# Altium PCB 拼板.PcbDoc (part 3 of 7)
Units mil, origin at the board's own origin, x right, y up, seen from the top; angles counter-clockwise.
Board outline 3630.03 x 5330.03 mil, 2 copper layers (Top Layer, Bottom Layer); 416 components, 35 nets, 1936 pads, 800 vias.
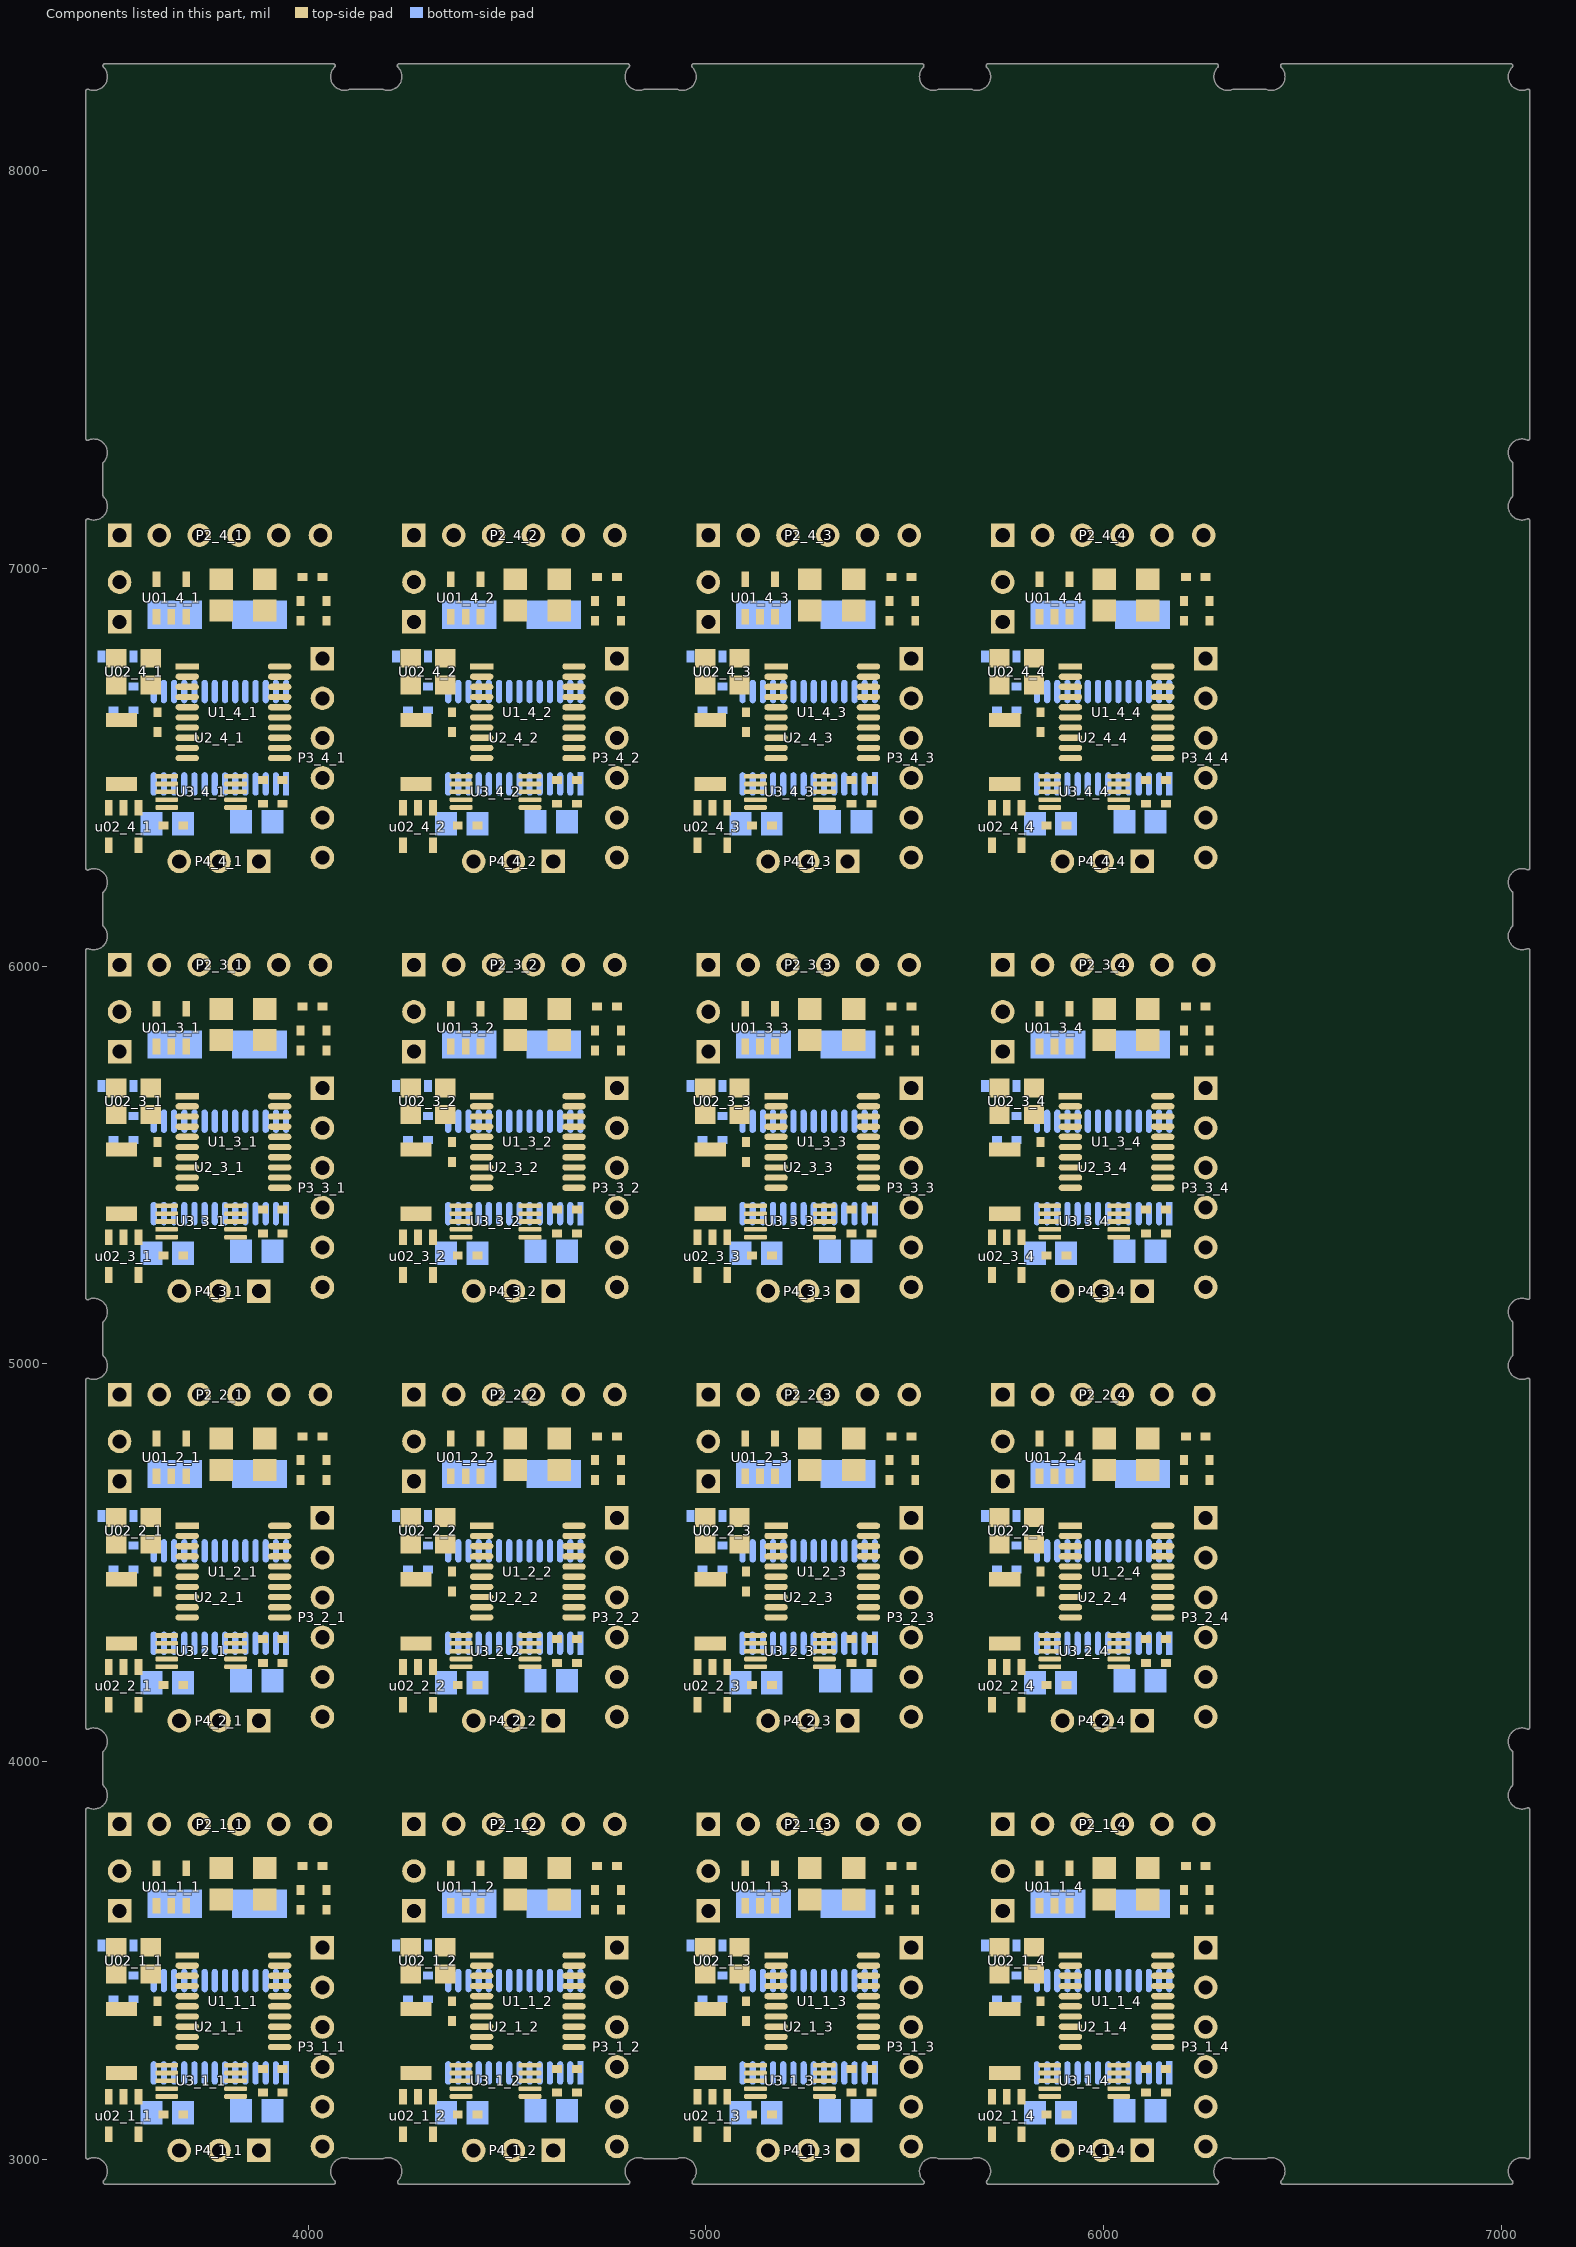
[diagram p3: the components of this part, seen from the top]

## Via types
v1: diameter 24, hole 24, Top Layer to Bottom Layer, 480 vias
v2: diameter 20, hole 10, Top Layer to Bottom Layer, 240 vias
v3: diameter 36, hole 20, Top Layer to Bottom Layer, 48 vias
v4: diameter 32, hole 16, Top Layer to Bottom Layer, 32 vias

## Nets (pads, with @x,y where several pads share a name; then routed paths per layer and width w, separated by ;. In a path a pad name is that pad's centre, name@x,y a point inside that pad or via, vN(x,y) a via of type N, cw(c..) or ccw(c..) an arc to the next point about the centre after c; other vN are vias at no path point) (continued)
copper on no net: | length 270841.8
  Top Layer w8: 3517.76,3466.64 3519.73,3466.64 3552.35,3499.26 3634.83,3499.26 3668.37,3465.71 3668.44,3465.71 3672.32,3461.84 3696.07,3461.84 ; 3517.76,4546.64 3519.73,4546.64 3552.35,4579.26 3634.83,4579.26 3668.37,4545.71 3668.44,4545.71 3672.32,4541.84 3696.07,4541.84 ; 3517.76,5626.64 3519.73,5626.64 3552.35,5659.26 3634.83,5659.26 3668.37,5625.71 3668.44,5625.71 3672.32,5621.84 3696.07,5621.84 ; 3517.76,6706.64 3519.73,6706.64 3552.35,6739.26 3634.83,6739.26 3668.37,6705.71 3668.44,6705.71 3672.32,6701.84 3696.07,6701.84 ; 3526.78,3378.02 3601.07,3378.02 3621.07,3398.02 3627.03,3392.06 3647.03,3392.06 3652.99,3386.1 3695.04,3386.1 3696.07,3385.07 ; 3526.78,4458.02 3601.07,4458.02 3621.07,4478.02 3627.03,4472.06 3647.03,4472.06 3652.99,4466.1 3695.04,4466.1 3696.07,4465.07 ; 3526.78,5538.02 3601.07,5538.02 3621.07,5558.02 3627.03,5552.06 3647.03,5552.06 3652.99,5546.1 3695.04,5546.1 3696.07,5545.07 ; 3526.78,6618.02 3601.07,6618.02 3621.07,6638.02 3627.03,6632.06 3647.03,6632.06 3652.99,6626.1 3695.04,6626.1 3696.07,6625.07 ; 3573.47,3083.53 3602.96,3113.02 3636.07,3113.02 ; 3573.47,4163.53 3602.96,4193.02 3636.07,4193.02 ; 3573.47,5243.53 3602.96,5273.02 3636.07,5273.02 ; 3573.47,6323.53 3602.96,6353.02 3636.07,6353.02 ; 3614.61,3523.34 3624,3513.95 3642.42,3513.95 3667.45,3488.91 3694.58,3488.91 3696.07,3487.43 ; 3614.61,4603.34 3624,4593.95 3642.42,4593.95 3667.45,4568.91 3694.58,4568.91 3696.07,4567.43 ; 3614.61,5683.34 3624,5673.95 3642.42,5673.95 3667.45,5648.91 3694.58,5648.91 3696.07,5647.43 ; 3614.61,6763.34 3624,6753.95 3642.42,6753.95 3667.45,6728.91 3694.58,6728.91 3696.07,6727.43 ; 3644.45,3158.65 3644.45,3119.02 3638.45,3113.02 3636.07,3113.02 ; 3644.45,3237.39 3749.65,3237.39 3820.56,3308.3 3928.35,3308.3 ; 3644.45,4238.65 3644.45,4199.02 3638.45,4193.02 3636.07,4193.02 ; 3644.45,4317.39 3749.65,4317.39 3820.56,4388.3 3928.35,4388.3 ; 3644.45,5318.65 3644.45,5279.02 3638.45,5273.02 3636.07,5273.02 ; 3644.45,5397.39 3749.65,5397.39 3820.56,5468.3 3928.35,5468.3 ; 3644.45,6398.65 3644.45,6359.02 3638.45,6353.02 3636.07,6353.02 ; 3644.45,6477.39 3749.65,6477.39 3820.56,6548.3 3928.35,6548.3 ; 3696.07,3282.71 3747.5,3282.71 3752.82,3288.02 v2(3756.07,3288.02) ; 3696.07,3308.3 3696.34,3308.02 v2(3736.07,3308.02) ; 3696.07,3333.89 3749.13,3333.89 3760.51,3322.51 v2(3796.07,3322.51) ; 3696.07,3359.48 3751.01,3359.48 3768.98,3341.51 v2(3771.48,3341.51) ; 3696.07,3513.02 3717.72,3513.02 v2(3752.72,3548.02) ; 3696.07,4362.71 3747.5,4362.71 3752.82,4368.02 v2(3756.07,4368.02) ; 3696.07,4388.3 3696.34,4388.02 v2(3736.07,4388.02) ; 3696.07,4413.89 3749.13,4413.89 3760.51,4402.51 v2(3796.07,4402.51) ; 3696.07,4439.48 3751.01,4439.48 3768.98,4421.51 v2(3771.48,4421.51) ; 3696.07,4593.02 3717.72,4593.02 v2(3752.72,4628.02) ; 3696.07,5442.71 3747.5,5442.71 3752.82,5448.02 v2(3756.07,5448.02) ; 3696.07,5468.3 3696.34,5468.02 v2(3736.07,5468.02) ; 3696.07,5493.89 3749.13,5493.89 3760.51,5482.51 v2(3796.07,5482.51) ; 3696.07,5519.48 3751.01,5519.48 3768.98,5501.51 v2(3771.48,5501.51) ; 3696.07,5673.02 3717.72,5673.02 v2(3752.72,5708.02) ; 3696.07,6522.71 3747.5,6522.71 3752.82,6528.02 v2(3756.07,6528.02) ; 3696.07,6548.3 3696.34,6548.02 v2(3736.07,6548.02) ; 3696.07,6573.89 3749.13,6573.89 3760.51,6562.51 v2(3796.07,6562.51) ; 3696.07,6599.48 3751.01,6599.48 3768.98,6581.51 v2(3771.48,6581.51) ; 3696.07,6753.02 3717.72,6753.02 v2(3752.72,6788.02) ; v2(3806.07,3548.02) 3892.25,3461.84 3928.35,3461.84 ; v2(3806.07,4628.02) 3892.25,4541.84 3928.35,4541.84 ; v2(3806.07,5708.02) 3892.25,5621.84 3928.35,5621.84 ; v2(3806.07,6788.02) 3892.25,6701.84 3928.35,6701.84 ; v2(3816.07,3413.02) 3878.74,3413.02 3906.7,3385.07 3928.35,3385.07 ; v2(3816.07,4493.02) 3878.74,4493.02 3906.7,4465.07 3928.35,4465.07 ; v2(3816.07,5573.02) 3878.74,5573.02 3906.7,5545.07 3928.35,5545.07 ; v2(3816.07,6653.02) 3878.74,6653.02 3906.7,6625.07 3928.35,6625.07 ; 3817.68,3158.65 3771.7,3158.65 3704,3090.96 3663.13,3090.96 3647.07,3107.02 3642.07,3107.02 3636.07,3113.02 ; 3817.68,3217.71 3816.85,3218.54 3784.82,3218.54 3780.14,3223.23 3780.14,3245.3 3830.14,3295.3 3868.19,3295.3 3880.78,3282.71 3928.35,3282.71 ; 3817.68,4238.65 3771.7,4238.65 3704,4170.96 3663.13,4170.96 3647.07,4187.02 3642.07,4187.02 3636.07,4193.02 ; 3817.68,4297.71 3816.85,4298.54 3784.82,4298.54 3780.14,4303.23 3780.14,4325.3 3830.14,4375.3 3868.19,4375.3 3880.78,4362.71 3928.35,4362.71 ; 3817.68,5318.65 3771.7,5318.65 3704,5250.96 3663.13,5250.96 3647.07,5267.02 3642.07,5267.02 3636.07,5273.02 ; 3817.68,5377.71 3816.85,5378.54 3784.82,5378.54 3780.14,5383.23 3780.14,5405.3 3830.14,5455.3 3868.19,5455.3 3880.78,5442.71 3928.35,5442.71 ; 3817.68,6398.65 3771.7,6398.65 3704,6330.96 3663.13,6330.96 3647.07,6347.02 3642.07,6347.02 3636.07,6353.02 ; 3817.68,6457.71 3816.85,6458.54 3784.82,6458.54 3780.14,6463.23 3780.14,6485.3 3830.14,6535.3 3868.19,6535.3 3880.78,6522.71 3928.35,6522.71 ; v2(3836.07,3373.02) 3846.07,3373.02 3883.72,3335.37 3926.87,3335.37 3928.35,3333.89 ; v2(3836.07,4453.02) 3846.07,4453.02 3883.72,4415.37 3926.87,4415.37 3928.35,4413.89 ; v2(3836.07,5533.02) 3846.07,5533.02 3883.72,5495.37 3926.87,5495.37 3928.35,5493.89 ; v2(3836.07,6613.02) 3846.07,6613.02 3883.72,6575.37 3926.87,6575.37 3928.35,6573.89 ; v2(3836.92,3548.02) 3836.92,3543.35 3892.84,3487.43 3928.35,3487.43 ; v2(3836.92,4628.02) 3836.92,4623.35 3892.84,4567.43 3928.35,4567.43 ; v2(3836.92,5708.02) 3836.92,5703.35 3892.84,5647.43 3928.35,5647.43 ; v2(3836.92,6788.02) 3836.92,6783.35 3892.84,6727.43 3928.35,6727.43 ; v2(3866.07,3390.52) 3866.07,3388.02 3893.13,3360.96 3926.87,3360.96 3928.35,3359.48 ; v2(3866.07,3548.02) 3866.07,3544.22 3895.92,3514.36 3927.02,3514.36 3928.35,3513.02 ; v2(3866.07,4470.52) 3866.07,4468.02 3893.13,4440.96 3926.87,4440.96 3928.35,4439.48 ; v2(3866.07,4628.02) 3866.07,4624.22 3895.92,4594.36 3927.02,4594.36 3928.35,4593.02 ; v2(3866.07,5550.52) 3866.07,5548.02 3893.13,5520.96 3926.87,5520.96 3928.35,5519.48 ; v2(3866.07,5708.02) 3866.07,5704.22 3895.92,5674.36 3927.02,5674.36 3928.35,5673.02 ; v2(3866.07,6630.52) 3866.07,6628.02 3893.13,6600.96 3926.87,6600.96 3928.35,6599.48 ; v2(3866.07,6788.02) 3866.07,6784.22 3895.92,6754.36 3927.02,6754.36 3928.35,6753.02 ; 3886.07,3168.02 3892.07,3174.02 3902.07,3174.02 v2(3921.07,3193.02) ; 3886.07,4248.02 3892.07,4254.02 3902.07,4254.02 v2(3921.07,4273.02) ; 3886.07,5328.02 3892.07,5334.02 3902.07,5334.02 v2(3921.07,5353.02) ; 3886.07,6408.02 3892.07,6414.02 3902.07,6414.02 v2(3921.07,6433.02) ; 3928.35,3410.66 3952.1,3410.66 4029.74,3333.02 4036.07,3333.02 ; 3928.35,3436.25 3929.83,3434.77 4034.32,3434.77 4036.07,3433.02 ; 3928.35,4490.66 3952.1,4490.66 4029.74,4413.02 4036.07,4413.02 ; 3928.35,4516.25 3929.83,4514.77 4034.32,4514.77 4036.07,4513.02 ; 3928.35,5570.66 3952.1,5570.66 4029.74,5493.02 4036.07,5493.02 ; 3928.35,5596.25 3929.83,5594.77 4034.32,5594.77 4036.07,5593.02 ; 3928.35,6650.66 3952.1,6650.66 4029.74,6573.02 4036.07,6573.02 ; 3928.35,6676.25 3929.83,6674.77 4034.32,6674.77 4036.07,6673.02 ; 3936.07,3168.02 3938.57,3168.02 3944.57,3174.02 3944.57,3183.27 3951.07,3189.77 v2(3951.07,3193.02) ; 3936.07,3228.02 3939.07,3225.02 3956.76,3225.02 3970.07,3211.72 3970.07,3144.02 v2(3976.07,3138.02) ; 3936.07,4248.02 3938.57,4248.02 3944.57,4254.02 3944.57,4263.27 3951.07,4269.77 v2(3951.07,4273.02) ; 3936.07,4308.02 3939.07,4305.02 3956.76,4305.02 3970.07,4291.72 3970.07,4224.02 v2(3976.07,4218.02) ; 3936.07,5328.02 3938.57,5328.02 3944.57,5334.02 3944.57,5343.27 3951.07,5349.77 v2(3951.07,5353.02) ; 3936.07,5388.02 3939.07,5385.02 3956.76,5385.02 3970.07,5371.72 3970.07,5304.02 v2(3976.07,5298.02) ; 3936.07,6408.02 3938.57,6408.02 3944.57,6414.02 3944.57,6423.27 3951.07,6429.77 v2(3951.07,6433.02) ; 3936.07,6468.02 3939.07,6465.02 3956.76,6465.02 3970.07,6451.72 3970.07,6384.02 v2(3976.07,6378.02) ; 4257.76,3466.64 4259.73,3466.64 4292.35,3499.26 4374.83,3499.26 4408.37,3465.71 4408.44,3465.71 4412.32,3461.84 4436.07,3461.84 ; 4257.76,4546.64 4259.73,4546.64 4292.35,4579.26 4374.83,4579.26 4408.37,4545.71 4408.44,4545.71 4412.32,4541.84 4436.07,4541.84 ; 4257.76,5626.64 4259.73,5626.64 4292.35,5659.26 4374.83,5659.26 4408.37,5625.71 4408.44,5625.71 4412.32,5621.84 4436.07,5621.84 ; 4257.76,6706.64 4259.73,6706.64 4292.35,6739.26 4374.83,6739.26 4408.37,6705.71 4408.44,6705.71 4412.32,6701.84 4436.07,6701.84 ; 4266.78,3378.02 4341.07,3378.02 4361.07,3398.02 4367.03,3392.06 4387.03,3392.06 4392.99,3386.1 4435.04,3386.1 4436.07,3385.07 ; 4266.78,4458.02 4341.07,4458.02 4361.07,4478.02 4367.03,4472.06 4387.03,4472.06 4392.99,4466.1 4435.04,4466.1 4436.07,4465.07 ; 4266.78,5538.02 4341.07,5538.02 4361.07,5558.02 4367.03,5552.06 4387.03,5552.06 4392.99,5546.1 4435.04,5546.1 4436.07,5545.07 ; 4266.78,6618.02 4341.07,6618.02 4361.07,6638.02 4367.03,6632.06 4387.03,6632.06 4392.99,6626.1 4435.04,6626.1 4436.07,6625.07 ; 4313.47,3083.53 4342.96,3113.02 4376.07,3113.02 ; 4313.47,4163.53 4342.96,4193.02 4376.07,4193.02 ; 4313.47,5243.53 4342.96,5273.02 4376.07,5273.02 ; 4313.47,6323.53 4342.96,6353.02 4376.07,6353.02 ; 4354.61,3523.34 4364,3513.95 4382.42,3513.95 4407.45,3488.91 4434.58,3488.91 4436.07,3487.43 ; 4354.61,4603.34 4364,4593.95 4382.42,4593.95 4407.45,4568.91 4434.58,4568.91 4436.07,4567.43 ; 4354.61,5683.34 4364,5673.95 4382.42,5673.95 4407.45,5648.91 4434.58,5648.91 4436.07,5647.43 ; 4354.61,6763.34 4364,6753.95 4382.42,6753.95 4407.45,6728.91 4434.58,6728.91 4436.07,6727.43 ; 4384.45,3158.65 4384.45,3119.02 4378.45,3113.02 4376.07,3113.02 ; 4384.45,3237.39 4489.65,3237.39 4560.56,3308.3 4668.35,3308.3 ; 4384.45,4238.65 4384.45,4199.02 4378.45,4193.02 4376.07,4193.02 ; 4384.45,4317.39 4489.65,4317.39 4560.56,4388.3 4668.35,4388.3 ; 4384.45,5318.65 4384.45,5279.02 4378.45,5273.02 4376.07,5273.02 ; 4384.45,5397.39 4489.65,5397.39 4560.56,5468.3 4668.35,5468.3 ; 4384.45,6398.65 4384.45,6359.02 4378.45,6353.02 4376.07,6353.02 ; 4384.45,6477.39 4489.65,6477.39 4560.56,6548.3 4668.35,6548.3 ; 4436.07,3282.71 4487.5,3282.71 4492.82,3288.02 v2(4496.07,3288.02) ; 4436.07,3308.3 4436.34,3308.02 v2(4476.07,3308.02) ; 4436.07,3333.89 4489.13,3333.89 4500.51,3322.51 v2(4536.07,3322.51) ; 4436.07,3359.48 4491.01,3359.48 4508.98,3341.51 v2(4511.48,3341.51) ; 4436.07,3513.02 4457.72,3513.02 v2(4492.72,3548.02) ; 4436.07,4362.71 4487.5,4362.71 4492.82,4368.02 v2(4496.07,4368.02) ; 4436.07,4388.3 4436.34,4388.02 v2(4476.07,4388.02) ; 4436.07,4413.89 4489.13,4413.89 4500.51,4402.51 v2(4536.07,4402.51) ; 4436.07,4439.48 4491.01,4439.48 4508.98,4421.51 v2(4511.48,4421.51) ; 4436.07,4593.02 4457.72,4593.02 v2(4492.72,4628.02) ; 4436.07,5442.71 4487.5,5442.71 4492.82,5448.02 v2(4496.07,5448.02) ; 4436.07,5468.3 4436.34,5468.02 v2(4476.07,5468.02) ; 4436.07,5493.89 4489.13,5493.89 4500.51,5482.51 v2(4536.07,5482.51) ; 4436.07,5519.48 4491.01,5519.48 4508.98,5501.51 v2(4511.48,5501.51) ; 4436.07,5673.02 4457.72,5673.02 v2(4492.72,5708.02) ; 4436.07,6522.71 4487.5,6522.71 4492.82,6528.02 v2(4496.07,6528.02) ; 4436.07,6548.3 4436.34,6548.02 v2(4476.07,6548.02) ; 4436.07,6573.89 4489.13,6573.89 4500.51,6562.51 v2(4536.07,6562.51) ; 4436.07,6599.48 4491.01,6599.48 4508.98,6581.51 v2(4511.48,6581.51) ; 4436.07,6753.02 4457.72,6753.02 v2(4492.72,6788.02) ; v2(4546.07,3548.02) 4632.25,3461.84 4668.35,3461.84 ; v2(4546.07,4628.02) 4632.25,4541.84 4668.35,4541.84 ; v2(4546.07,5708.02) 4632.25,5621.84 4668.35,5621.84 ; v2(4546.07,6788.02) 4632.25,6701.84 4668.35,6701.84 ; v2(4556.07,3413.02) 4618.74,3413.02 4646.7,3385.07 4668.35,3385.07 ; v2(4556.07,4493.02) 4618.74,4493.02 4646.7,4465.07 4668.35,4465.07 ; v2(4556.07,5573.02) 4618.74,5573.02 4646.7,5545.07 4668.35,5545.07 ; v2(4556.07,6653.02) 4618.74,6653.02 4646.7,6625.07 4668.35,6625.07 ; 4557.68,3158.65 4511.7,3158.65 4444,3090.96 4403.13,3090.96 4387.07,3107.02 4382.07,3107.02 4376.07,3113.02 ; 4557.68,3217.71 4556.85,3218.54 4524.82,3218.54 4520.14,3223.23 4520.14,3245.3 4570.14,3295.3 4608.19,3295.3 4620.78,3282.71 4668.35,3282.71 ; 4557.68,4238.65 4511.7,4238.65 4444,4170.96 4403.13,4170.96 4387.07,4187.02 4382.07,4187.02 4376.07,4193.02 ; 4557.68,4297.71 4556.85,4298.54 4524.82,4298.54 4520.14,4303.23 4520.14,4325.3 4570.14,4375.3 4608.19,4375.3 4620.78,4362.71 4668.35,4362.71 ; 4557.68,5318.65 4511.7,5318.65 4444,5250.96 4403.13,5250.96 4387.07,5267.02 4382.07,5267.02 4376.07,5273.02 ; 4557.68,5377.71 4556.85,5378.54 4524.82,5378.54 4520.14,5383.23 4520.14,5405.3 4570.14,5455.3 4608.19,5455.3 4620.78,5442.71 4668.35,5442.71 ; 4557.68,6398.65 4511.7,6398.65 4444,6330.96 4403.13,6330.96 4387.07,6347.02 4382.07,6347.02 4376.07,6353.02 ; 4557.68,6457.71 4556.85,6458.54 4524.82,6458.54 4520.14,6463.23 4520.14,6485.3 4570.14,6535.3 4608.19,6535.3 4620.78,6522.71 4668.35,6522.71 ; v2(4576.07,3373.02) 4586.07,3373.02 4623.72,3335.37 4666.87,3335.37 4668.35,3333.89 ; v2(4576.07,4453.02) 4586.07,4453.02 4623.72,4415.37 4666.87,4415.37 4668.35,4413.89 ; v2(4576.07,5533.02) 4586.07,5533.02 4623.72,5495.37 4666.87,5495.37 4668.35,5493.89 ; v2(4576.07,6613.02) 4586.07,6613.02 4623.72,6575.37 4666.87,6575.37 4668.35,6573.89 ; v2(4576.92,3548.02) 4576.92,3543.35 4632.84,3487.43 4668.35,3487.43 ; v2(4576.92,4628.02) 4576.92,4623.35 4632.84,4567.43 4668.35,4567.43 ; v2(4576.92,5708.02) 4576.92,5703.35 4632.84,5647.43 4668.35,5647.43 ; v2(4576.92,6788.02) 4576.92,6783.35 4632.84,6727.43 4668.35,6727.43 ; v2(4606.07,3390.52) 4606.07,3388.02 4633.13,3360.96 4666.87,3360.96 4668.35,3359.48 ; v2(4606.07,3548.02) 4606.07,3544.22 4635.92,3514.36 4667.02,3514.36 4668.35,3513.02 ; v2(4606.07,4470.52) 4606.07,4468.02 4633.13,4440.96 4666.87,4440.96 4668.35,4439.48 ; v2(4606.07,4628.02) 4606.07,4624.22 4635.92,4594.36 4667.02,4594.36 4668.35,4593.02 ; v2(4606.07,5550.52) 4606.07,5548.02 4633.13,5520.96 4666.87,5520.96 4668.35,5519.48 ; v2(4606.07,5708.02) 4606.07,5704.22 4635.92,5674.36 4667.02,5674.36 4668.35,5673.02 ; v2(4606.07,6630.52) 4606.07,6628.02 4633.13,6600.96 4666.87,6600.96 4668.35,6599.48 ; v2(4606.07,6788.02) 4606.07,6784.22 4635.92,6754.36 4667.02,6754.36 4668.35,6753.02 ; 4626.07,3168.02 4632.07,3174.02 4642.07,3174.02 v2(4661.07,3193.02) ; 4626.07,4248.02 4632.07,4254.02 4642.07,4254.02 v2(4661.07,4273.02) ; 4626.07,5328.02 4632.07,5334.02 4642.07,5334.02 v2(4661.07,5353.02) ; 4626.07,6408.02 4632.07,6414.02 4642.07,6414.02 v2(4661.07,6433.02) ; 4668.35,3410.66 4692.1,3410.66 4769.74,3333.02 4776.07,3333.02 ; 4668.35,3436.25 4669.83,3434.77 4774.32,3434.77 4776.07,3433.02 ; 4668.35,4490.66 4692.1,4490.66 4769.74,4413.02 4776.07,4413.02 ; 4668.35,4516.25 4669.83,4514.77 4774.32,4514.77 4776.07,4513.02 ; 4668.35,5570.66 4692.1,5570.66 4769.74,5493.02 4776.07,5493.02 ; 4668.35,5596.25 4669.83,5594.77 4774.32,5594.77 4776.07,5593.02 ; 4668.35,6650.66 4692.1,6650.66 4769.74,6573.02 4776.07,6573.02 ; 4668.35,6676.25 4669.83,6674.77 4774.32,6674.77 4776.07,6673.02 ; 4676.07,3168.02 4678.57,3168.02 4684.57,3174.02 4684.57,3183.27 4691.07,3189.77 v2(4691.07,3193.02) ; 4676.07,3228.02 4679.07,3225.02 4696.76,3225.02 4710.07,3211.72 4710.07,3144.02 v2(4716.07,3138.02) ; 4676.07,4248.02 4678.57,4248.02 4684.57,4254.02 4684.57,4263.27 4691.07,4269.77 v2(4691.07,4273.02) ; 4676.07,4308.02 4679.07,4305.02 4696.76,4305.02 4710.07,4291.72 4710.07,4224.02 v2(4716.07,4218.02) ; 4676.07,5328.02 4678.57,5328.02 4684.57,5334.02 4684.57,5343.27 4691.07,5349.77 v2(4691.07,5353.02) ; 4676.07,5388.02 4679.07,5385.02 4696.76,5385.02 4710.07,5371.72 4710.07,5304.02 v2(4716.07,5298.02) ; 4676.07,6408.02 4678.57,6408.02 4684.57,6414.02 4684.57,6423.27 4691.07,6429.77 v2(4691.07,6433.02) ; 4676.07,6468.02 4679.07,6465.02 4696.76,6465.02 4710.07,6451.72 4710.07,6384.02 v2(4716.07,6378.02) ; 4997.76,3466.64 4999.73,3466.64 5032.35,3499.26 5114.83,3499.26 5148.37,3465.71 5148.44,3465.71 5152.32,3461.84 5176.07,3461.84 ; 4997.76,4546.64 4999.73,4546.64 5032.35,4579.26 5114.83,4579.26 5148.37,4545.71 5148.44,4545.71 5152.32,4541.84 5176.07,4541.84 ; 4997.76,5626.64 4999.73,5626.64 5032.35,5659.26 5114.83,5659.26 5148.37,5625.71 5148.44,5625.71 5152.32,5621.84 5176.07,5621.84 ; 4997.76,6706.64 4999.73,6706.64 5032.35,6739.26 5114.83,6739.26 5148.37,6705.71 5148.44,6705.71 5152.32,6701.84 5176.07,6701.84 ; 5006.78,3378.02 5081.07,3378.02 5101.07,3398.02 5107.03,3392.06 5127.03,3392.06 5132.99,3386.1 5175.04,3386.1 5176.07,3385.07 ; 5006.78,4458.02 5081.07,4458.02 5101.07,4478.02 5107.03,4472.06 5127.03,4472.06 5132.99,4466.1 5175.04,4466.1 5176.07,4465.07 ; 5006.78,5538.02 5081.07,5538.02 5101.07,5558.02 5107.03,5552.06 5127.03,5552.06 5132.99,5546.1 5175.04,5546.1 5176.07,5545.07 ; 5006.78,6618.02 5081.07,6618.02 5101.07,6638.02 5107.03,6632.06 5127.03,6632.06 5132.99,6626.1 5175.04,6626.1 5176.07,6625.07 ; 5053.47,3083.53 5082.96,3113.02 5116.07,3113.02 ; 5053.47,4163.53 5082.96,4193.02 5116.07,4193.02 ; 5053.47,5243.53 5082.96,5273.02 5116.07,5273.02 ; 5053.47,6323.53 5082.96,6353.02 5116.07,6353.02 ; 5094.61,3523.34 5104,3513.95 5122.42,3513.95 5147.45,3488.91 5174.58,3488.91 5176.07,3487.43 ; 5094.61,4603.34 5104,4593.95 5122.42,4593.95 5147.45,4568.91 5174.58,4568.91 5176.07,4567.43 ; 5094.61,5683.34 5104,5673.95 5122.42,5673.95 5147.45,5648.91 5174.58,5648.91 5176.07,5647.43 ; 5094.61,6763.34 5104,6753.95 5122.42,6753.95 5147.45,6728.91 5174.58,6728.91 5176.07,6727.43 ; 5124.45,3158.65 5124.45,3119.02 5118.45,3113.02 5116.07,3113.02 ; 5124.45,3237.39 5229.65,3237.39 5300.56,3308.3 5408.35,3308.3 ; 5124.45,4238.65 5124.45,4199.02 5118.45,4193.02 5116.07,4193.02 ; 5124.45,4317.39 5229.65,4317.39 5300.56,4388.3 5408.35,4388.3 ; 5124.45,5318.65 5124.45,5279.02 5118.45,5273.02 5116.07,5273.02 ; 5124.45,5397.39 5229.65,5397.39 5300.56,5468.3 5408.35,5468.3 ; 5124.45,6398.65 5124.45,6359.02 5118.45,6353.02 5116.07,6353.02 ; 5124.45,6477.39 5229.65,6477.39 5300.56,6548.3 5408.35,6548.3 ; 5176.07,3282.71 5227.5,3282.71 5232.82,3288.02 v2(5236.07,3288.02) ; 5176.07,3308.3 5176.34,3308.02 v2(5216.07,3308.02) ; 5176.07,3333.89 5229.13,3333.89 5240.51,3322.51 v2(5276.07,3322.51) ; 5176.07,3359.48 5231.01,3359.48 5248.98,3341.51 v2(5251.48,3341.51) ; 5176.07,3513.02 5197.72,3513.02 v2(5232.72,3548.02) ; 5176.07,4362.71 5227.5,4362.71 5232.82,4368.02 v2(5236.07,4368.02) ; 5176.07,4388.3 5176.34,4388.02 v2(5216.07,4388.02) ; 5176.07,4413.89 5229.13,4413.89 5240.51,4402.51 v2(5276.07,4402.51) ; 5176.07,4439.48 5231.01,4439.48 5248.98,4421.51 v2(5251.48,4421.51) ; 5176.07,4593.02 5197.72,4593.02 v2(5232.72,4628.02) ; 5176.07,5442.71 5227.5,5442.71 5232.82,5448.02 v2(5236.07,5448.02) ; 5176.07,5468.3 5176.34,5468.02 v2(5216.07,5468.02) ; 5176.07,5493.89 5229.13,5493.89 5240.51,5482.51 v2(5276.07,5482.51) ; 5176.07,5519.48 5231.01,5519.48 5248.98,5501.51 v2(5251.48,5501.51) ; 5176.07,5673.02 5197.72,5673.02 v2(5232.72,5708.02) ; 5176.07,6522.71 5227.5,6522.71 5232.82,6528.02 v2(5236.07,6528.02) ; 5176.07,6548.3 5176.34,6548.02 v2(5216.07,6548.02) ; 5176.07,6573.89 5229.13,6573.89 5240.51,6562.51 v2(5276.07,6562.51) ; 5176.07,6599.48 5231.01,6599.48 5248.98,6581.51 v2(5251.48,6581.51) ; 5176.07,6753.02 5197.72,6753.02 v2(5232.72,6788.02) ; v2(5286.07,3548.02) 5372.25,3461.84 5408.35,3461.84 ; v2(5286.07,4628.02) 5372.25,4541.84 5408.35,4541.84 ; v2(5286.07,5708.02) 5372.25,5621.84 5408.35,5621.84 ; v2(5286.07,6788.02) 5372.25,6701.84 5408.35,6701.84 ; v2(5296.07,3413.02) 5358.74,3413.02 5386.7,3385.07 5408.35,3385.07 ; v2(5296.07,4493.02) 5358.74,4493.02 5386.7,4465.07 5408.35,4465.07 ; v2(5296.07,5573.02) 5358.74,5573.02 5386.7,5545.07 5408.35,5545.07 ; v2(5296.07,6653.02) 5358.74,6653.02 5386.7,6625.07 5408.35,6625.07 ; 5297.68,3158.65 5251.7,3158.65 5184,3090.96 5143.13,3090.96 5127.07,3107.02 5122.07,3107.02 5116.07,3113.02 ; 5297.68,3217.71 5296.85,3218.54 5264.82,3218.54 5260.14,3223.23 5260.14,3245.3 5310.14,3295.3 5348.19,3295.3 5360.78,3282.71 5408.35,3282.71 ; 5297.68,4238.65 5251.7,4238.65 5184,4170.96 5143.13,4170.96 5127.07,4187.02 5122.07,4187.02 5116.07,4193.02 ; 5297.68,4297.71 5296.85,4298.54 5264.82,4298.54 5260.14,4303.23 5260.14,4325.3 5310.14,4375.3 5348.19,4375.3 5360.78,4362.71 5408.35,4362.71 ; 5297.68,5318.65 5251.7,5318.65 5184,5250.96 5143.13,5250.96 5127.07,5267.02 5122.07,5267.02 5116.07,5273.02 ; 5297.68,5377.71 5296.85,5378.54 5264.82,5378.54 5260.14,5383.23 5260.14,5405.3 5310.14,5455.3 5348.19,5455.3 5360.78,5442.71 5408.35,5442.71 ; 5297.68,6398.65 5251.7,6398.65 5184,6330.96 5143.13,6330.96 5127.07,6347.02 5122.07,6347.02 5116.07,6353.02 ; 5297.68,6457.71 5296.85,6458.54 5264.82,6458.54 5260.14,6463.23 5260.14,6485.3 5310.14,6535.3 5348.19,6535.3 5360.78,6522.71 5408.35,6522.71 ; v2(5316.07,3373.02) 5326.07,3373.02 5363.72,3335.37 5406.87,3335.37 5408.35,3333.89 ; v2(5316.07,4453.02) 5326.07,4453.02 5363.72,4415.37 5406.87,4415.37 5408.35,4413.89 ; v2(5316.07,5533.02) 5326.07,5533.02 5363.72,5495.37 5406.87,5495.37 5408.35,5493.89 ; v2(5316.07,6613.02) 5326.07,6613.02 5363.72,6575.37 5406.87,6575.37 5408.35,6573.89 ; v2(5316.92,3548.02) 5316.92,3543.35 5372.84,3487.43 5408.35,3487.43 ; v2(5316.92,4628.02) 5316.92,4623.35 5372.84,4567.43 5408.35,4567.43 ; v2(5316.92,5708.02) 5316.92,5703.35 5372.84,5647.43 5408.35,5647.43 ; v2(5316.92,6788.02) 5316.92,6783.35 5372.84,6727.43 5408.35,6727.43 ; v2(5346.07,3390.52) 5346.07,3388.02 5373.13,3360.96 5406.87,3360.96 5408.35,3359.48 ; v2(5346.07,3548.02) 5346.07,3544.22 5375.92,3514.36 5407.02,3514.36 5408.35,3513.02 ; v2(5346.07,4470.52) 5346.07,4468.02 5373.13,4440.96 5406.87,4440.96 5408.35,4439.48 ; v2(5346.07,4628.02) 5346.07,4624.22 5375.92,4594.36 5407.02,4594.36 5408.35,4593.02 ; v2(5346.07,5550.52) 5346.07,5548.02 5373.13,5520.96 5406.87,5520.96 5408.35,5519.48 ; v2(5346.07,5708.02) 5346.07,5704.22 5375.92,5674.36 5407.02,5674.36 5408.35,5673.02 ; v2(5346.07,6630.52) 5346.07,6628.02 5373.13,6600.96 5406.87,6600.96 5408.35,6599.48 ; v2(5346.07,6788.02) 5346.07,6784.22 5375.92,6754.36 5407.02,6754.36 5408.35,6753.02 ; 5366.07,3168.02 5372.07,3174.02 5382.07,3174.02 v2(5401.07,3193.02) ; 5366.07,4248.02 5372.07,4254.02 5382.07,4254.02 v2(5401.07,4273.02) ; 5366.07,5328.02 5372.07,5334.02 5382.07,5334.02 v2(5401.07,5353.02) ; 5366.07,6408.02 5372.07,6414.02 5382.07,6414.02 v2(5401.07,6433.02) ; 5408.35,3410.66 5432.1,3410.66 5509.74,3333.02 5516.07,3333.02 ; 5408.35,3436.25 5409.83,3434.77 5514.32,3434.77 5516.07,3433.02 ; 5408.35,4490.66 5432.1,4490.66 5509.74,4413.02 5516.07,4413.02 ; 5408.35,4516.25 5409.83,4514.77 5514.32,4514.77 5516.07,4513.02 ; 5408.35,5570.66 5432.1,5570.66 5509.74,5493.02 5516.07,5493.02 ; 5408.35,5596.25 5409.83,5594.77 5514.32,5594.77 5516.07,5593.02 ; 5408.35,6650.66 5432.1,6650.66 5509.74,6573.02 5516.07,6573.02 ; 5408.35,6676.25 5409.83,6674.77 5514.32,6674.77 5516.07,6673.02 ; 5416.07,3168.02 5418.57,3168.02 5424.57,3174.02 5424.57,3183.27 5431.07,3189.77 v2(5431.07,3193.02) ; 5416.07,3228.02 5419.07,3225.02 5436.76,3225.02 5450.07,3211.72 5450.07,3144.02 v2(5456.07,3138.02) ; 5416.07,4248.02 5418.57,4248.02 5424.57,4254.02 5424.57,4263.27 5431.07,4269.77 v2(5431.07,4273.02) ; 5416.07,4308.02 5419.07,4305.02 5436.76,4305.02 5450.07,4291.72 5450.07,4224.02 v2(5456.07,4218.02) ; 5416.07,5328.02 5418.57,5328.02 5424.57,5334.02 5424.57,5343.27 5431.07,5349.77 v2(5431.07,5353.02) ; 5416.07,5388.02 5419.07,5385.02 5436.76,5385.02 5450.07,5371.72 5450.07,5304.02 v2(5456.07,5298.02) ; 5416.07,6408.02 5418.57,6408.02 5424.57,6414.02 5424.57,6423.27 5431.07,6429.77 v2(5431.07,6433.02) ; 5416.07,6468.02 5419.07,6465.02 5436.76,6465.02 5450.07,6451.72 5450.07,6384.02 v2(5456.07,6378.02) ; 5737.76,3466.64 5739.73,3466.64 5772.35,3499.26 5854.83,3499.26 5888.37,3465.71 5888.44,3465.71 5892.32,3461.84 5916.07,3461.84 ; 5737.76,4546.64 5739.73,4546.64 5772.35,4579.26 5854.83,4579.26 5888.37,4545.71 5888.44,4545.71 5892.32,4541.84 5916.07,4541.84 ; 5737.76,5626.64 5739.73,5626.64 5772.35,5659.26 5854.83,5659.26 5888.37,5625.71 5888.44,5625.71 5892.32,5621.84 5916.07,5621.84 ; 5737.76,6706.64 5739.73,6706.64 5772.35,6739.26 5854.83,6739.26 5888.37,6705.71 5888.44,6705.71 5892.32,6701.84 5916.07,6701.84 ; 5746.78,3378.02 5821.07,3378.02 5841.07,3398.02 5847.03,3392.06 5867.03,3392.06 5872.99,3386.1 5915.04,3386.1 5916.07,3385.07 ; 5746.78,4458.02 5821.07,4458.02 5841.07,4478.02 5847.03,4472.06 5867.03,4472.06 5872.99,4466.1 5915.04,4466.1 5916.07,4465.07 ; 5746.78,5538.02 5821.07,5538.02 5841.07,5558.02 5847.03,5552.06 5867.03,5552.06 5872.99,5546.1 5915.04,5546.1 5916.07,5545.07 ; 5746.78,6618.02 5821.07,6618.02 5841.07,6638.02 5847.03,6632.06 5867.03,6632.06 5872.99,6626.1 5915.04,6626.1 5916.07,6625.07 ; 5793.47,3083.53 5822.96,3113.02 5856.07,3113.02 ; 5793.47,4163.53 5822.96,4193.02 5856.07,4193.02 ; 5793.47,5243.53 5822.96,5273.02 5856.07,5273.02 ; 5793.47,6323.53 5822.96,6353.02 5856.07,6353.02 ; 5834.61,3523.34 5844,3513.95 5862.42,3513.95 5887.45,3488.91 5914.58,3488.91 5916.07,3487.43 ; 5834.61,4603.34 5844,4593.95 5862.42,4593.95 5887.45,4568.91 5914.58,4568.91 5916.07,4567.43 ; 5834.61,5683.34 5844,5673.95 5862.42,5673.95 5887.45,5648.91 5914.58,5648.91 5916.07,5647.43 ; 5834.61,6763.34 5844,6753.95 5862.42,6753.95 5887.45,6728.91 5914.58,6728.91 5916.07,6727.43 ; 5864.45,3158.65 5864.45,3119.02 5858.45,3113.02 5856.07,3113.02 ; 5864.45,3237.39 5969.65,3237.39 6040.56,3308.3 6148.35,3308.3 ; 5864.45,4238.65 5864.45,4199.02 5858.45,4193.02 5856.07,4193.02 ; 5864.45,4317.39 5969.65,4317.39 6040.56,4388.3 6148.35,4388.3 ; 5864.45,5318.65 5864.45,5279.02 5858.45,5273.02 5856.07,5273.02 ; 5864.45,5397.39 5969.65,5397.39 6040.56,5468.3 6148.35,5468.3 ; 5864.45,6398.65 5864.45,6359.02 5858.45,6353.02 5856.07,6353.02 ; 5864.45,6477.39 5969.65,6477.39 6040.56,6548.3 6148.35,6548.3 ; 5916.07,3282.71 5967.5,3282.71 5972.82,3288.02 v2(5976.07,3288.02) ; 5916.07,3308.3 5916.34,3308.02 v2(5956.07,3308.02) ; 5916.07,3333.89 5969.13,3333.89 5980.51,3322.51 v2(6016.07,3322.51) ; 5916.07,3359.48 5971.01,3359.48 5988.98,3341.51 v2(5991.48,3341.51) ; 5916.07,3513.02 5937.72,3513.02 v2(5972.72,3548.02) ; 5916.07,4362.71 5967.5,4362.71 5972.82,4368.02 v2(5976.07,4368.02) ; 5916.07,4388.3 5916.34,4388.02 v2(5956.07,4388.02) ; 5916.07,4413.89 5969.13,4413.89 5980.51,4402.51 v2(6016.07,4402.51) ; 5916.07,4439.48 5971.01,4439.48 5988.98,4421.51 v2(5991.48,4421.51) ; 5916.07,4593.02 5937.72,4593.02 v2(5972.72,4628.02) ; 5916.07,5442.71 5967.5,5442.71 5972.82,5448.02 v2(5976.07,5448.02) ; 5916.07,5468.3 5916.34,5468.02 v2(5956.07,5468.02) ; 5916.07,5493.89 5969.13,5493.89 5980.51,5482.51 v2(6016.07,5482.51) ; 5916.07,5519.48 5971.01,5519.48 5988.98,5501.51 v2(5991.48,5501.51) ; 5916.07,5673.02 5937.72,5673.02 v2(5972.72,5708.02) ; 5916.07,6522.71 5967.5,6522.71 5972.82,6528.02 v2(5976.07,6528.02) ; 5916.07,6548.3 5916.34,6548.02 v2(5956.07,6548.02) ; 5916.07,6573.89 5969.13,6573.89 5980.51,6562.51 v2(6016.07,6562.51) ; 5916.07,6599.48 5971.01,6599.48 5988.98,6581.51 v2(5991.48,6581.51) ; 5916.07,6753.02 5937.72,6753.02 v2(5972.72,6788.02) ; v2(6026.07,3548.02) 6112.25,3461.84 6148.35,3461.84 ; v2(6026.07,4628.02) 6112.25,4541.84 6148.35,4541.84 ; v2(6026.07,5708.02) 6112.25,5621.84 6148.35,5621.84 ; v2(6026.07,6788.02) 6112.25,6701.84 6148.35,6701.84 ; v2(6036.07,3413.02) 6098.74,3413.02 6126.7,3385.07 6148.35,3385.07 ; v2(6036.07,4493.02) 6098.74,4493.02 6126.7,4465.07 6148.35,4465.07 ; v2(6036.07,5573.02) 6098.74,5573.02 6126.7,5545.07 6148.35,5545.07 ; v2(6036.07,6653.02) 6098.74,6653.02 6126.7,6625.07 6148.35,6625.07 ; 6037.68,3158.65 5991.7,3158.65 5924,3090.96 5883.13,3090.96 5867.07,3107.02 5862.07,3107.02 5856.07,3113.02 ; 6037.68,3217.71 6036.85,3218.54 6004.82,3218.54 6000.14,3223.23 6000.14,3245.3 6050.14,3295.3 6088.19,3295.3 6100.78,3282.71 6148.35,3282.71 ; 6037.68,4238.65 5991.7,4238.65 5924,4170.96 5883.13,4170.96 5867.07,4187.02 5862.07,4187.02 5856.07,4193.02 ; 6037.68,4297.71 6036.85,4298.54 6004.82,4298.54 6000.14,4303.23 6000.14,4325.3 6050.14,4375.3 6088.19,4375.3 6100.78,4362.71 6148.35,4362.71 ; 6037.68,5318.65 5991.7,5318.65 5924,5250.96 5883.13,5250.96 5867.07,5267.02 5862.07,5267.02 5856.07,5273.02 ; 6037.68,5377.71 6036.85,5378.54 6004.82,5378.54 6000.14,5383.23 6000.14,5405.3 6050.14,5455.3 6088.19,5455.3 6100.78,5442.71 6148.35,5442.71 ; 6037.68,6398.65 5991.7,6398.65 5924,6330.96 5883.13,6330.96 5867.07,6347.02 5862.07,6347.02 5856.07,6353.02 ; 6037.68,6457.71 6036.85,6458.54 6004.82,6458.54 6000.14,6463.23 6000.14,6485.3 6050.14,6535.3 6088.19,6535.3 6100.78,6522.71 6148.35,6522.71 ; v2(6056.07,3373.02) 6066.07,3373.02 6103.72,3335.37 6146.87,3335.37 6148.35,3333.89 ; v2(6056.07,4453.02) 6066.07,4453.02 6103.72,4415.37 6146.87,4415.37 6148.35,4413.89 ; v2(6056.07,5533.02) 6066.07,5533.02 6103.72,5495.37 6146.87,5495.37 6148.35,5493.89 ; v2(6056.07,6613.02) 6066.07,6613.02 6103.72,6575.37 6146.87,6575.37 6148.35,6573.89 ; v2(6056.92,3548.02) 6056.92,3543.35 6112.84,3487.43 6148.35,3487.43 ; v2(6056.92,4628.02) 6056.92,4623.35 6112.84,4567.43 6148.35,4567.43 ; v2(6056.92,5708.02) 6056.92,5703.35 6112.84,5647.43 6148.35,5647.43 ; v2(6056.92,6788.02) 6056.92,6783.35 6112.84,6727.43 6148.35,6727.43 ; v2(6086.07,3390.52) 6086.07,3388.02 6113.13,3360.96 6146.87,3360.96 6148.35,3359.48 ; v2(6086.07,3548.02) 6086.07,3544.22 6115.92,3514.36 6147.02,3514.36 6148.35,3513.02 ; v2(6086.07,4470.52) 6086.07,4468.02 6113.13,4440.96 6146.87,4440.96 6148.35,4439.48 ; v2(6086.07,4628.02) 6086.07,4624.22 6115.92,4594.36 6147.02,4594.36 6148.35,4593.02 ; v2(6086.07,5550.52) 6086.07,5548.02 6113.13,5520.96 6146.87,5520.96 6148.35,5519.48 ; v2(6086.07,5708.02) 6086.07,5704.22 6115.92,5674.36 6147.02,5674.36 6148.35,5673.02 ; v2(6086.07,6630.52) 6086.07,6628.02 6113.13,6600.96 6146.87,6600.96 6148.35,6599.48 ; v2(6086.07,6788.02) 6086.07,6784.22 6115.92,6754.36 6147.02,6754.36 6148.35,6753.02 ; 6106.07,3168.02 6112.07,3174.02 6122.07,3174.02 v2(6141.07,3193.02) ; 6106.07,4248.02 6112.07,4254.02 6122.07,4254.02 v2(6141.07,4273.02) ; 6106.07,5328.02 6112.07,5334.02 6122.07,5334.02 v2(6141.07,5353.02) ; 6106.07,6408.02 6112.07,6414.02 6122.07,6414.02 v2(6141.07,6433.02) ; 6148.35,3410.66 6172.1,3410.66 6249.74,3333.02 6256.07,3333.02 ; 6148.35,3436.25 6149.83,3434.77 6254.32,3434.77 6256.07,3433.02 ; 6148.35,4490.66 6172.1,4490.66 6249.74,4413.02 6256.07,4413.02 ; 6148.35,4516.25 6149.83,4514.77 6254.32,4514.77 6256.07,4513.02 ; 6148.35,5570.66 6172.1,5570.66 6249.74,5493.02 6256.07,5493.02 ; 6148.35,5596.25 6149.83,5594.77 6254.32,5594.77 6256.07,5593.02 ; 6148.35,6650.66 6172.1,6650.66 6249.74,6573.02 6256.07,6573.02 ; 6148.35,6676.25 6149.83,6674.77 6254.32,6674.77 6256.07,6673.02 ; 6156.07,3168.02 6158.57,3168.02 6164.57,3174.02 6164.57,3183.27 6171.07,3189.77 v2(6171.07,3193.02) ; 6156.07,3228.02 6159.07,3225.02 6176.76,3225.02 6190.07,3211.72 6190.07,3144.02 v2(6196.07,3138.02) ; 6156.07,4248.02 6158.57,4248.02 6164.57,4254.02 6164.57,4263.27 6171.07,4269.77 v2(6171.07,4273.02) ; 6156.07,4308.02 6159.07,4305.02 6176.76,4305.02 6190.07,4291.72 6190.07,4224.02 v2(6196.07,4218.02) ; 6156.07,5328.02 6158.57,5328.02 6164.57,5334.02 6164.57,5343.27 6171.07,5349.77 v2(6171.07,5353.02) ; 6156.07,5388.02 6159.07,5385.02 6176.76,5385.02 6190.07,5371.72 6190.07,5304.02 v2(6196.07,5298.02) ; 6156.07,6408.02 6158.57,6408.02 6164.57,6414.02 6164.57,6423.27 6171.07,6429.77 v2(6171.07,6433.02) ; 6156.07,6468.02 6159.07,6465.02 6176.76,6465.02 6190.07,6451.72 6190.07,6384.02 v2(6196.07,6378.02)
  Top Layer w12: 3817.68,3237.39 3817.77,3237.3 3846.37,3237.3 3857.69,3225.98 3857.69,3218.34 3869.01,3207.02 3903.12,3207.02 3912.57,3216.47 3912.57,3242.58 3919.01,3249.02 3962.75,3249.02 3995.54,3216.24 4028.75,3183.02 4063.07,3183.02 4088.07,3158.02 ; 3817.68,4317.39 3817.77,4317.3 3846.37,4317.3 3857.69,4305.98 3857.69,4298.34 3869.01,4287.02 3903.12,4287.02 3912.57,4296.47 3912.57,4322.58 3919.01,4329.02 3962.75,4329.02 3995.54,4296.24 4028.75,4263.02 4063.07,4263.02 4088.07,4238.02 ; 3817.68,5397.39 3817.77,5397.3 3846.37,5397.3 3857.69,5385.98 3857.69,5378.34 3869.01,5367.02 3903.12,5367.02 3912.57,5376.47 3912.57,5402.58 3919.01,5409.02 3962.75,5409.02 3995.54,5376.24 4028.75,5343.02 4063.07,5343.02 4088.07,5318.02 ; 3817.68,6477.39 3817.77,6477.3 3846.37,6477.3 3857.69,6465.98 3857.69,6458.34 3869.01,6447.02 3903.12,6447.02 3912.57,6456.47 3912.57,6482.58 3919.01,6489.02 3962.75,6489.02 3995.54,6456.24 4028.75,6423.02 4063.07,6423.02 4088.07,6398.02 ; 4557.68,3237.39 4557.77,3237.3 4586.37,3237.3 4597.69,3225.98 4597.69,3218.34 4609.01,3207.02 4643.12,3207.02 4652.57,3216.47 4652.57,3242.58 4659.01,3249.02 4702.75,3249.02 4735.54,3216.24 4768.75,3183.02 4803.07,3183.02 4828.07,3158.02 ; 4557.68,4317.39 4557.77,4317.3 4586.37,4317.3 4597.69,4305.98 4597.69,4298.34 4609.01,4287.02 4643.12,4287.02 4652.57,4296.47 4652.57,4322.58 4659.01,4329.02 4702.75,4329.02 4735.54,4296.24 4768.75,4263.02 4803.07,4263.02 4828.07,4238.02 ; 4557.68,5397.39 4557.77,5397.3 4586.37,5397.3 4597.69,5385.98 4597.69,5378.34 4609.01,5367.02 4643.12,5367.02 4652.57,5376.47 4652.57,5402.58 4659.01,5409.02 4702.75,5409.02 4735.54,5376.24 4768.75,5343.02 4803.07,5343.02 4828.07,5318.02 ; 4557.68,6477.39 4557.77,6477.3 4586.37,6477.3 4597.69,6465.98 4597.69,6458.34 4609.01,6447.02 4643.12,6447.02 4652.57,6456.47 4652.57,6482.58 4659.01,6489.02 4702.75,6489.02 4735.54,6456.24 4768.75,6423.02 4803.07,6423.02 4828.07,6398.02 ; 5297.68,3237.39 5297.77,3237.3 5326.37,3237.3 5337.69,3225.98 5337.69,3218.34 5349.01,3207.02 5383.12,3207.02 5392.57,3216.47 5392.57,3242.58 5399.01,3249.02 5442.75,3249.02 5475.54,3216.24 5508.75,3183.02 5543.07,3183.02 5568.07,3158.02 ; 5297.68,4317.39 5297.77,4317.3 5326.37,4317.3 5337.69,4305.98 5337.69,4298.34 5349.01,4287.02 5383.12,4287.02 5392.57,4296.47 5392.57,4322.58 5399.01,4329.02 5442.75,4329.02 5475.54,4296.24 5508.75,4263.02 5543.07,4263.02 5568.07,4238.02 ; 5297.68,5397.39 5297.77,5397.3 5326.37,5397.3 5337.69,5385.98 5337.69,5378.34 5349.01,5367.02 5383.12,5367.02 5392.57,5376.47 5392.57,5402.58 5399.01,5409.02 5442.75,5409.02 5475.54,5376.24 5508.75,5343.02 5543.07,5343.02 5568.07,5318.02 ; 5297.68,6477.39 5297.77,6477.3 5326.37,6477.3 5337.69,6465.98 5337.69,6458.34 5349.01,6447.02 5383.12,6447.02 5392.57,6456.47 5392.57,6482.58 5399.01,6489.02 5442.75,6489.02 5475.54,6456.24 5508.75,6423.02 5543.07,6423.02 5568.07,6398.02 ; 6037.68,3237.39 6037.77,3237.3 6066.37,3237.3 6077.69,3225.98 6077.69,3218.34 6089.01,3207.02 6123.12,3207.02 6132.57,3216.47 6132.57,3242.58 6139.01,3249.02 6182.75,3249.02 6215.54,3216.24 6248.75,3183.02 6283.07,3183.02 6308.07,3158.02 ; 6037.68,4317.39 6037.77,4317.3 6066.37,4317.3 6077.69,4305.98 6077.69,4298.34 6089.01,4287.02 6123.12,4287.02 6132.57,4296.47 6132.57,4322.58 6139.01,4329.02 6182.75,4329.02 6215.54,4296.24 6248.75,4263.02 6283.07,4263.02 6308.07,4238.02 ; 6037.68,5397.39 6037.77,5397.3 6066.37,5397.3 6077.69,5385.98 6077.69,5378.34 6089.01,5367.02 6123.12,5367.02 6132.57,5376.47 6132.57,5402.58 6139.01,5409.02 6182.75,5409.02 6215.54,5376.24 6248.75,5343.02 6283.07,5343.02 6308.07,5318.02 ; 6037.68,6477.39 6037.77,6477.3 6066.37,6477.3 6077.69,6465.98 6077.69,6458.34 6089.01,6447.02 6123.12,6447.02 6132.57,6456.47 6132.57,6482.58 6139.01,6489.02 6182.75,6489.02 6215.54,6456.24 6248.75,6423.02 6283.07,6423.02 6308.07,6398.02
  Top Layer w15: 3981.07,3628.02 4046.07,3628.02 ; 3981.07,4708.02 4046.07,4708.02 ; 3981.07,5788.02 4046.07,5788.02 ; 3981.07,6868.02 4046.07,6868.02 ; 4721.07,3628.02 4786.07,3628.02 ; 4721.07,4708.02 4786.07,4708.02 ; 4721.07,5788.02 4786.07,5788.02 ; 4721.07,6868.02 4786.07,6868.02 ; 5461.07,3628.02 5526.07,3628.02 ; 5461.07,4708.02 5526.07,4708.02 ; 5461.07,5788.02 5526.07,5788.02 ; 5461.07,6868.02 5526.07,6868.02 ; 6201.07,3628.02 6266.07,3628.02 ; 6201.07,4708.02 6266.07,4708.02 ; 6201.07,5788.02 6266.07,5788.02 ; 6201.07,6868.02 6266.07,6868.02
